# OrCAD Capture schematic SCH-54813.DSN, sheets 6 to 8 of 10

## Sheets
6 09 LEVEL SHIFT: size C
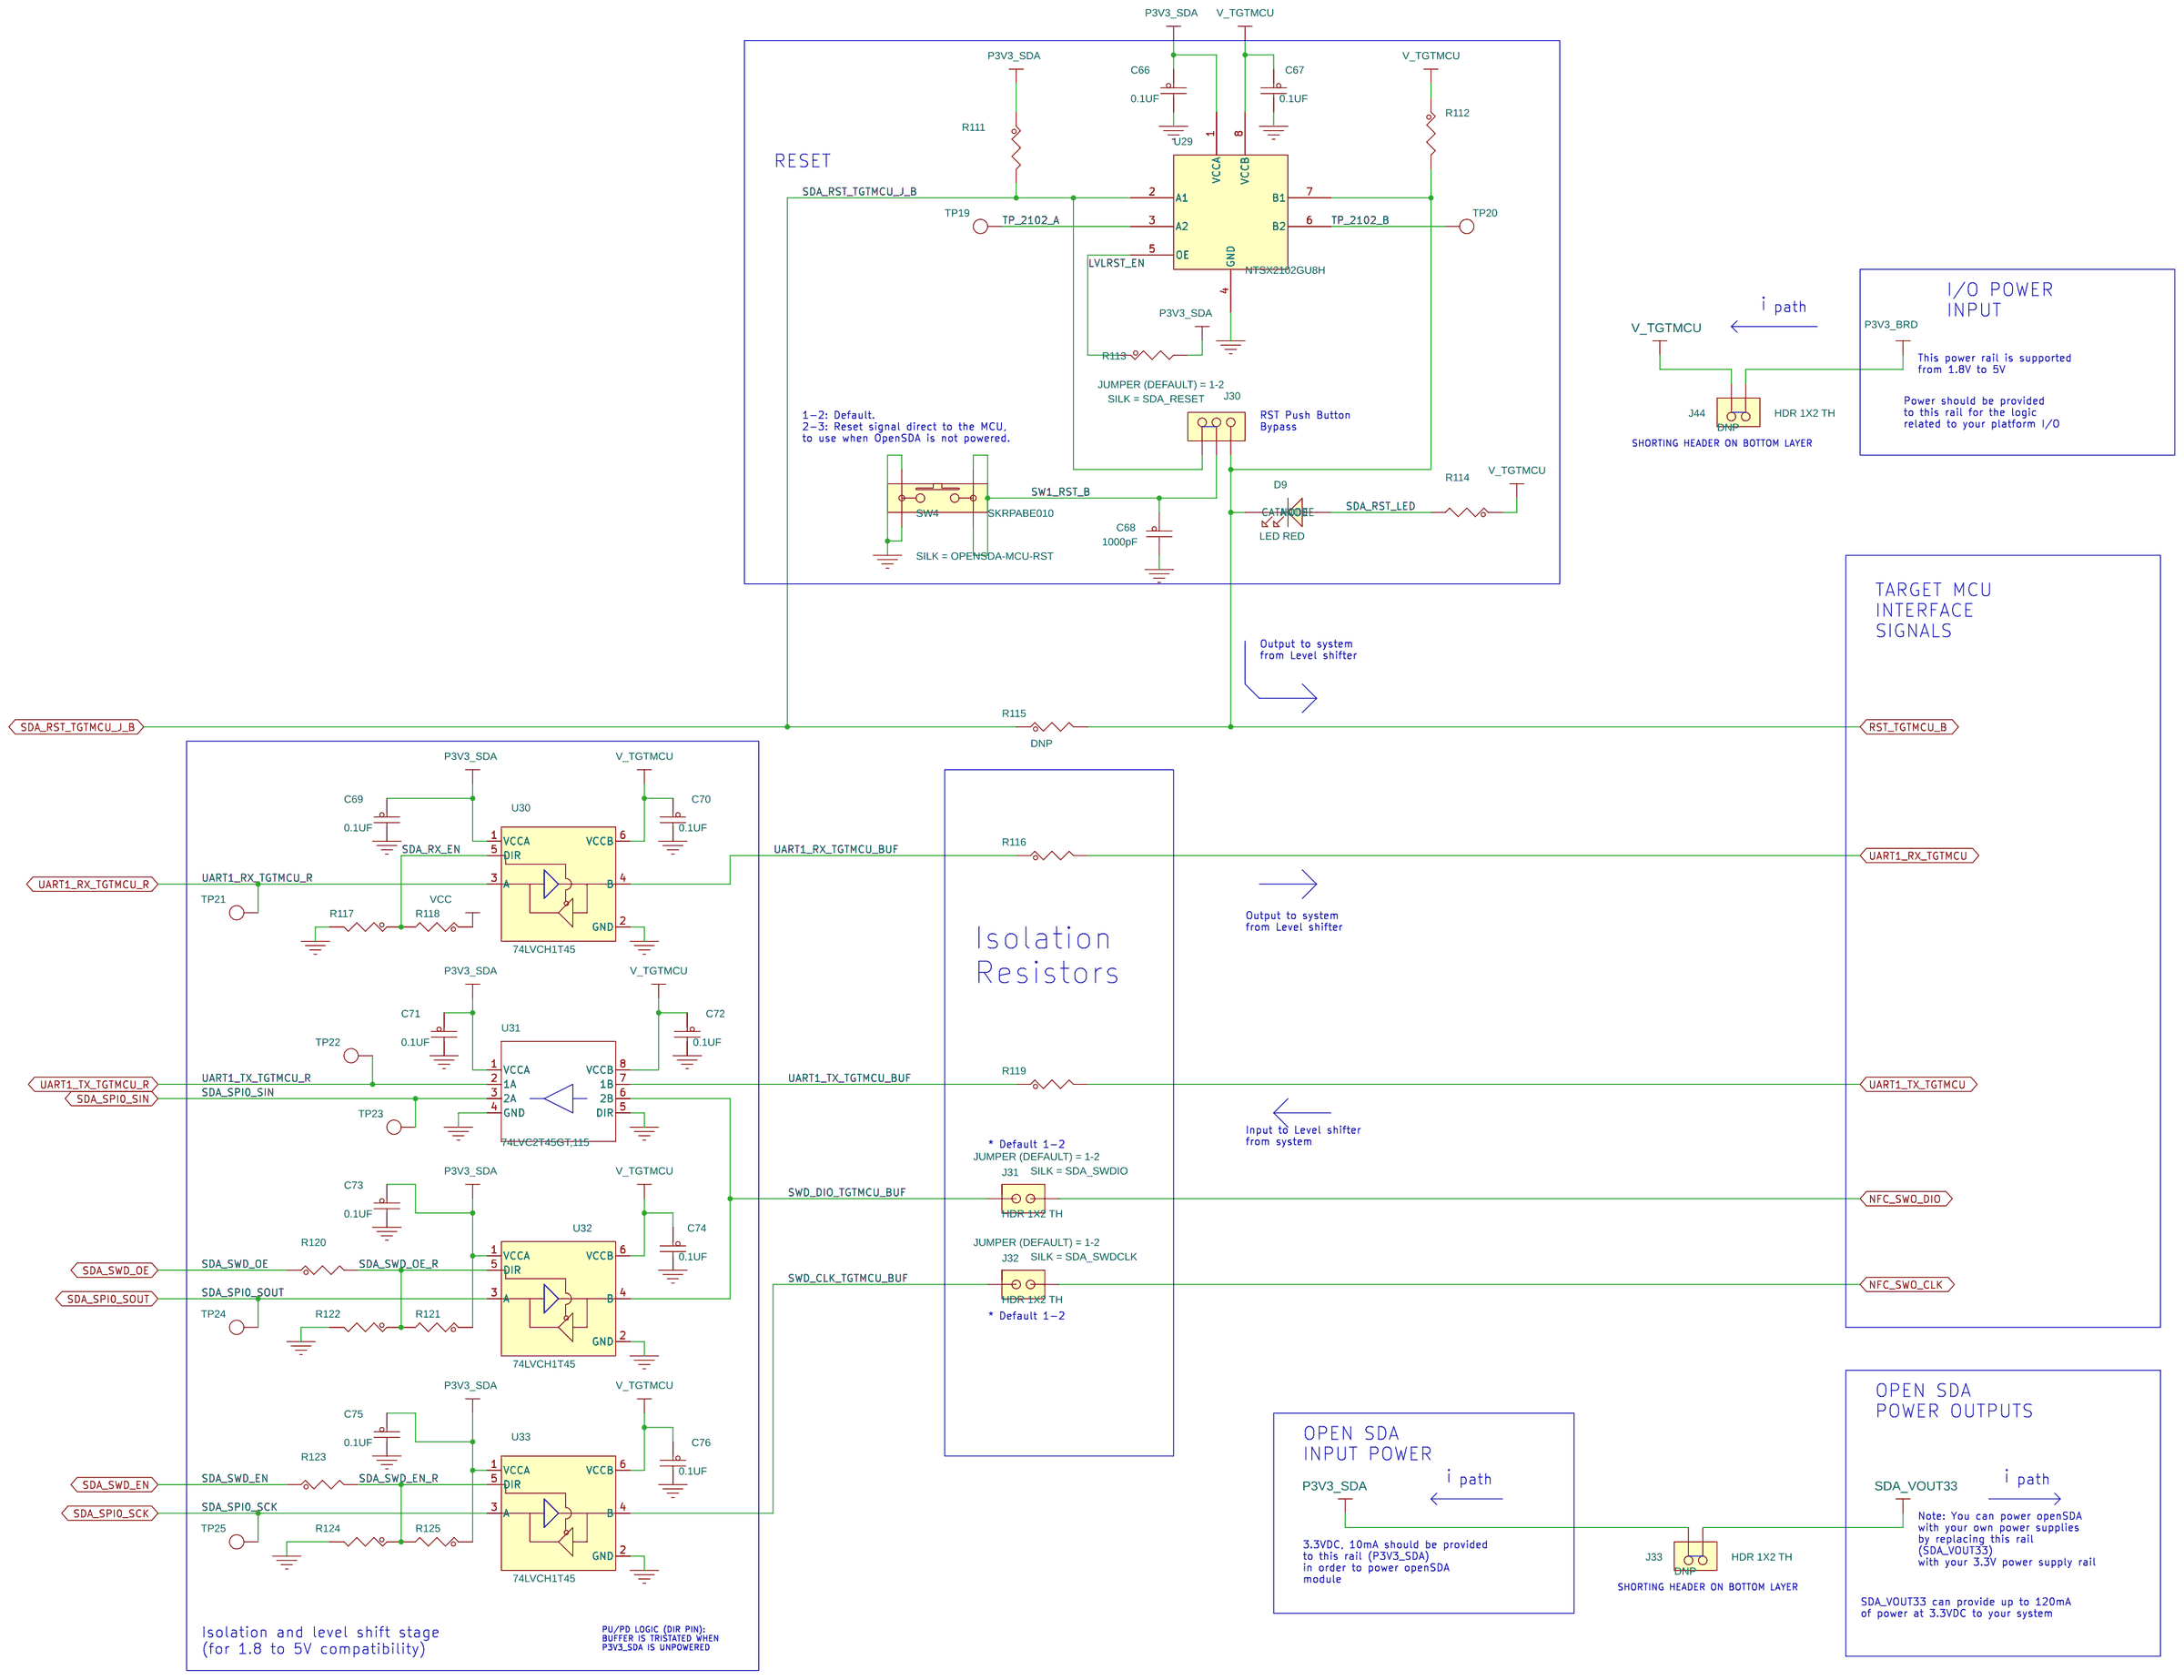
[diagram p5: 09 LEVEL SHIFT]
7 10 ARDUINO: size C
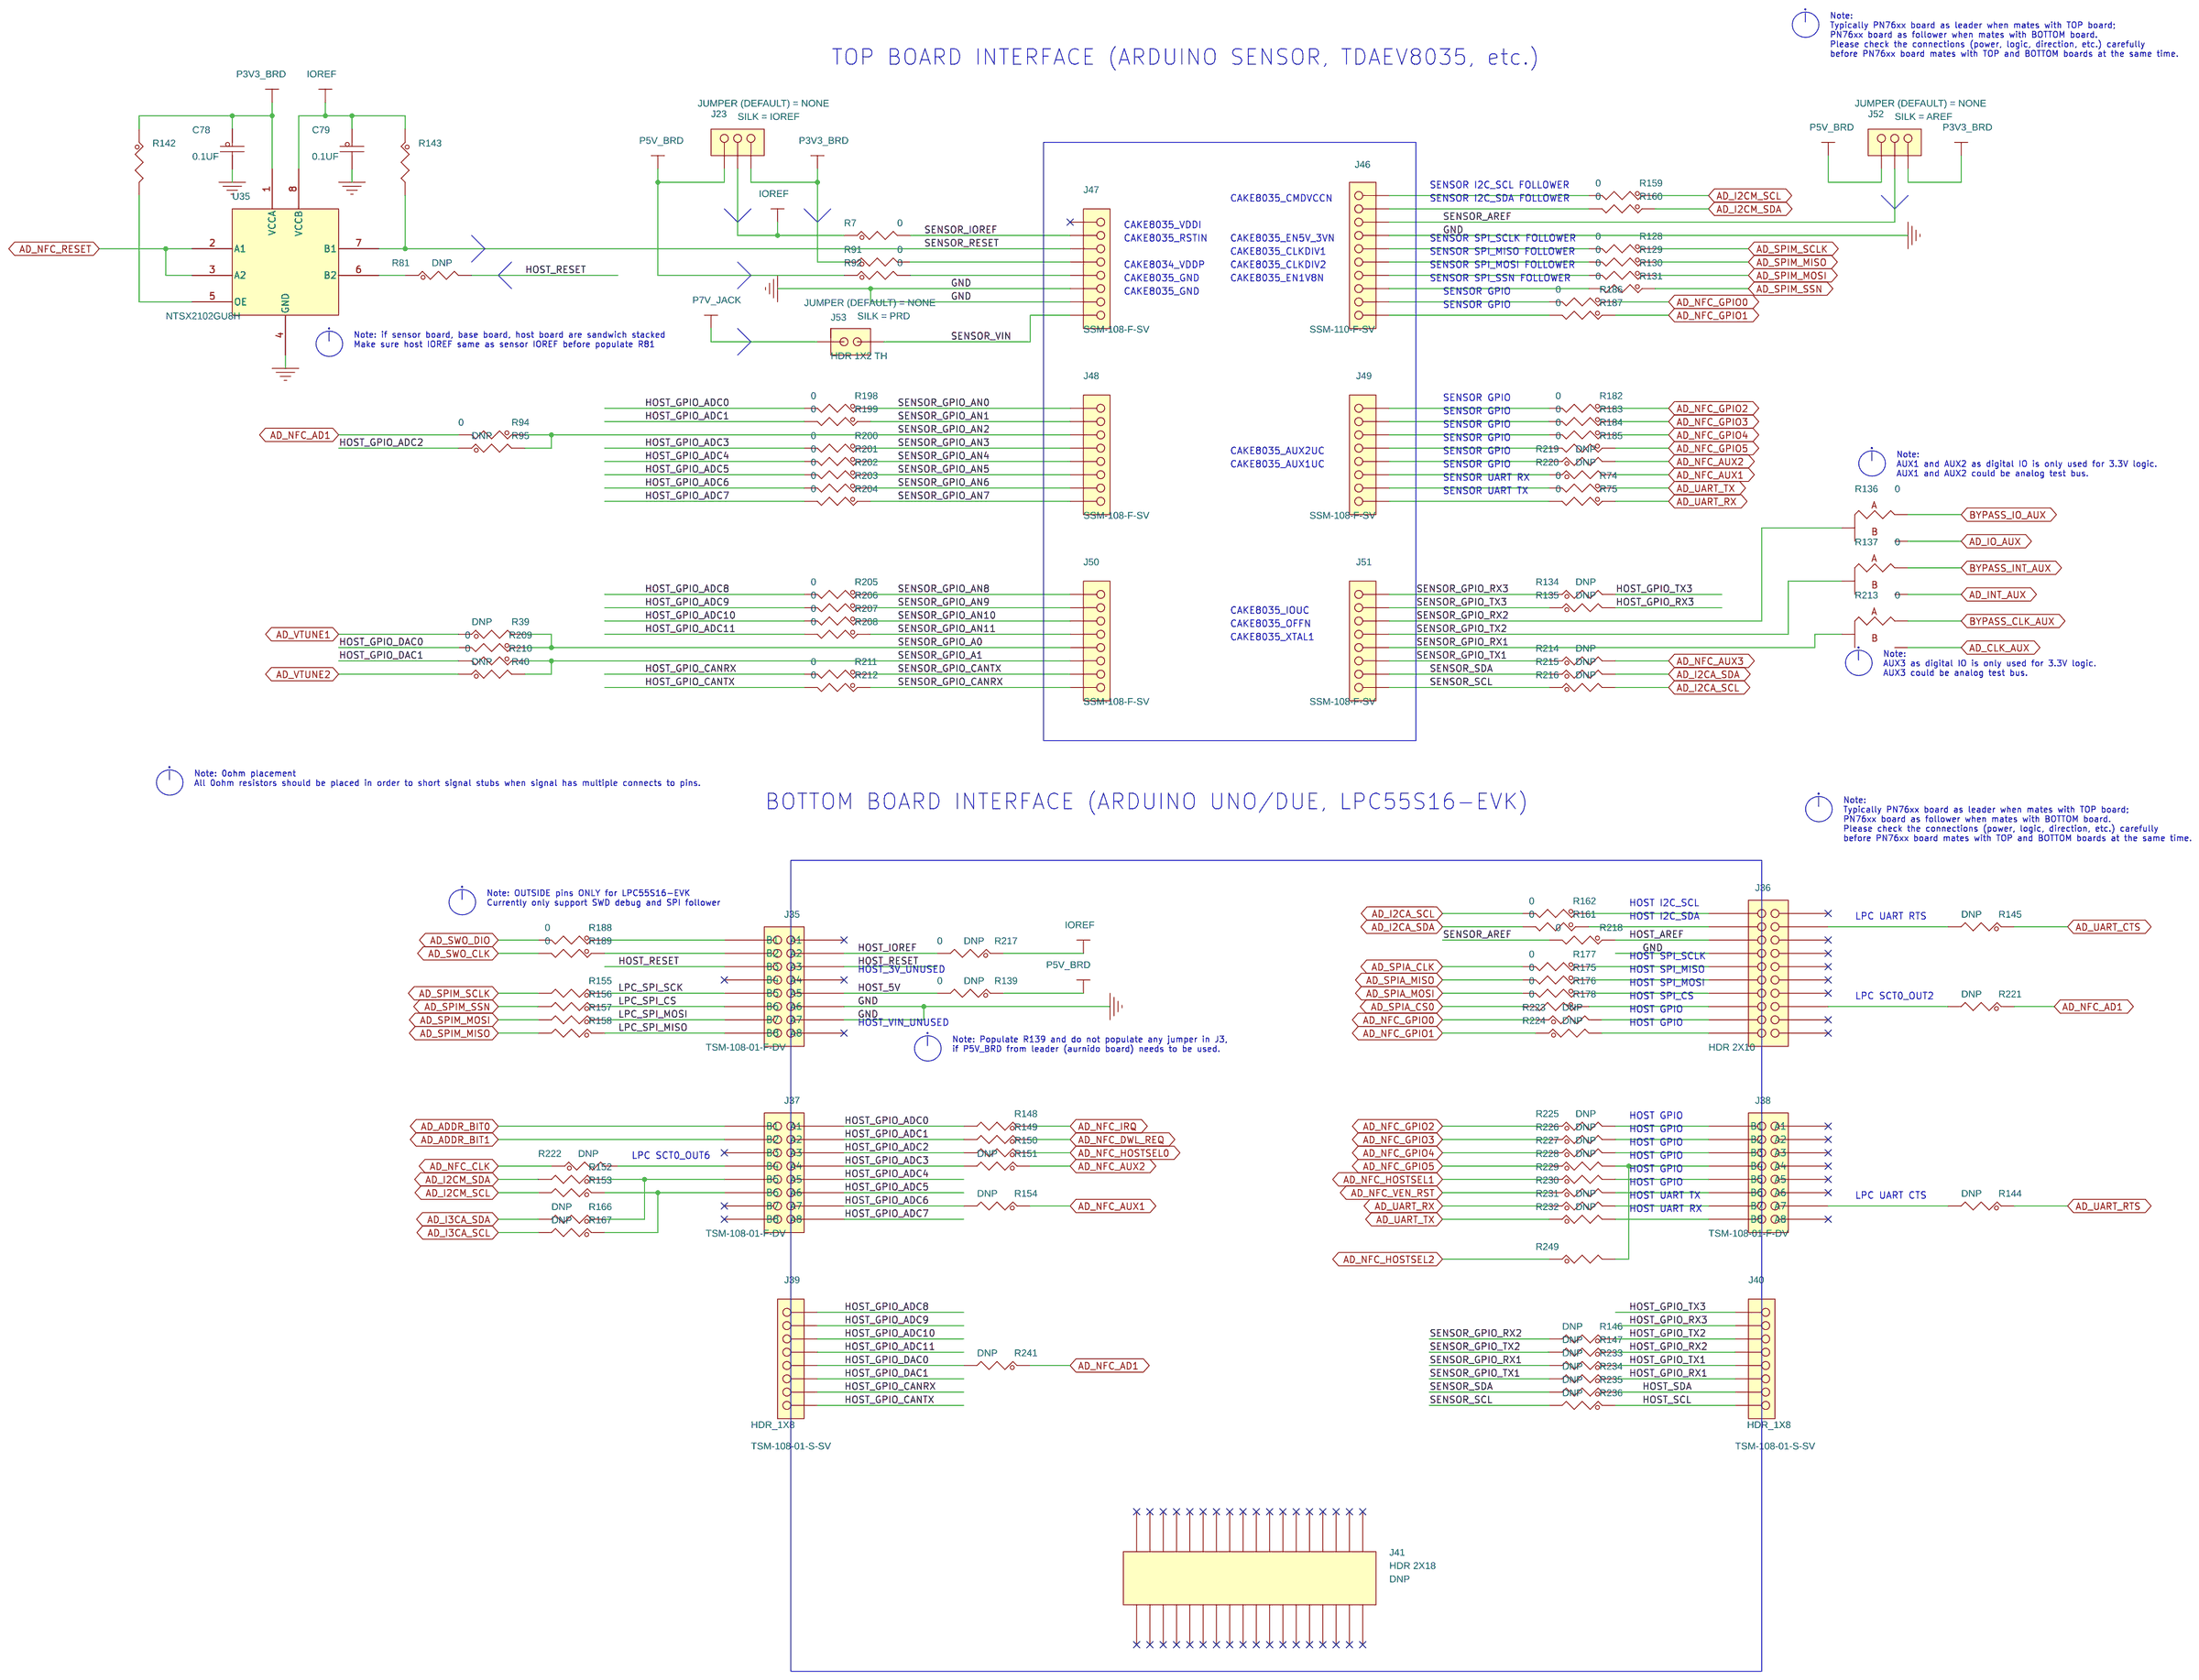
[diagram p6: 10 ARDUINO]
8 06 GPIO/DEBUG: size C
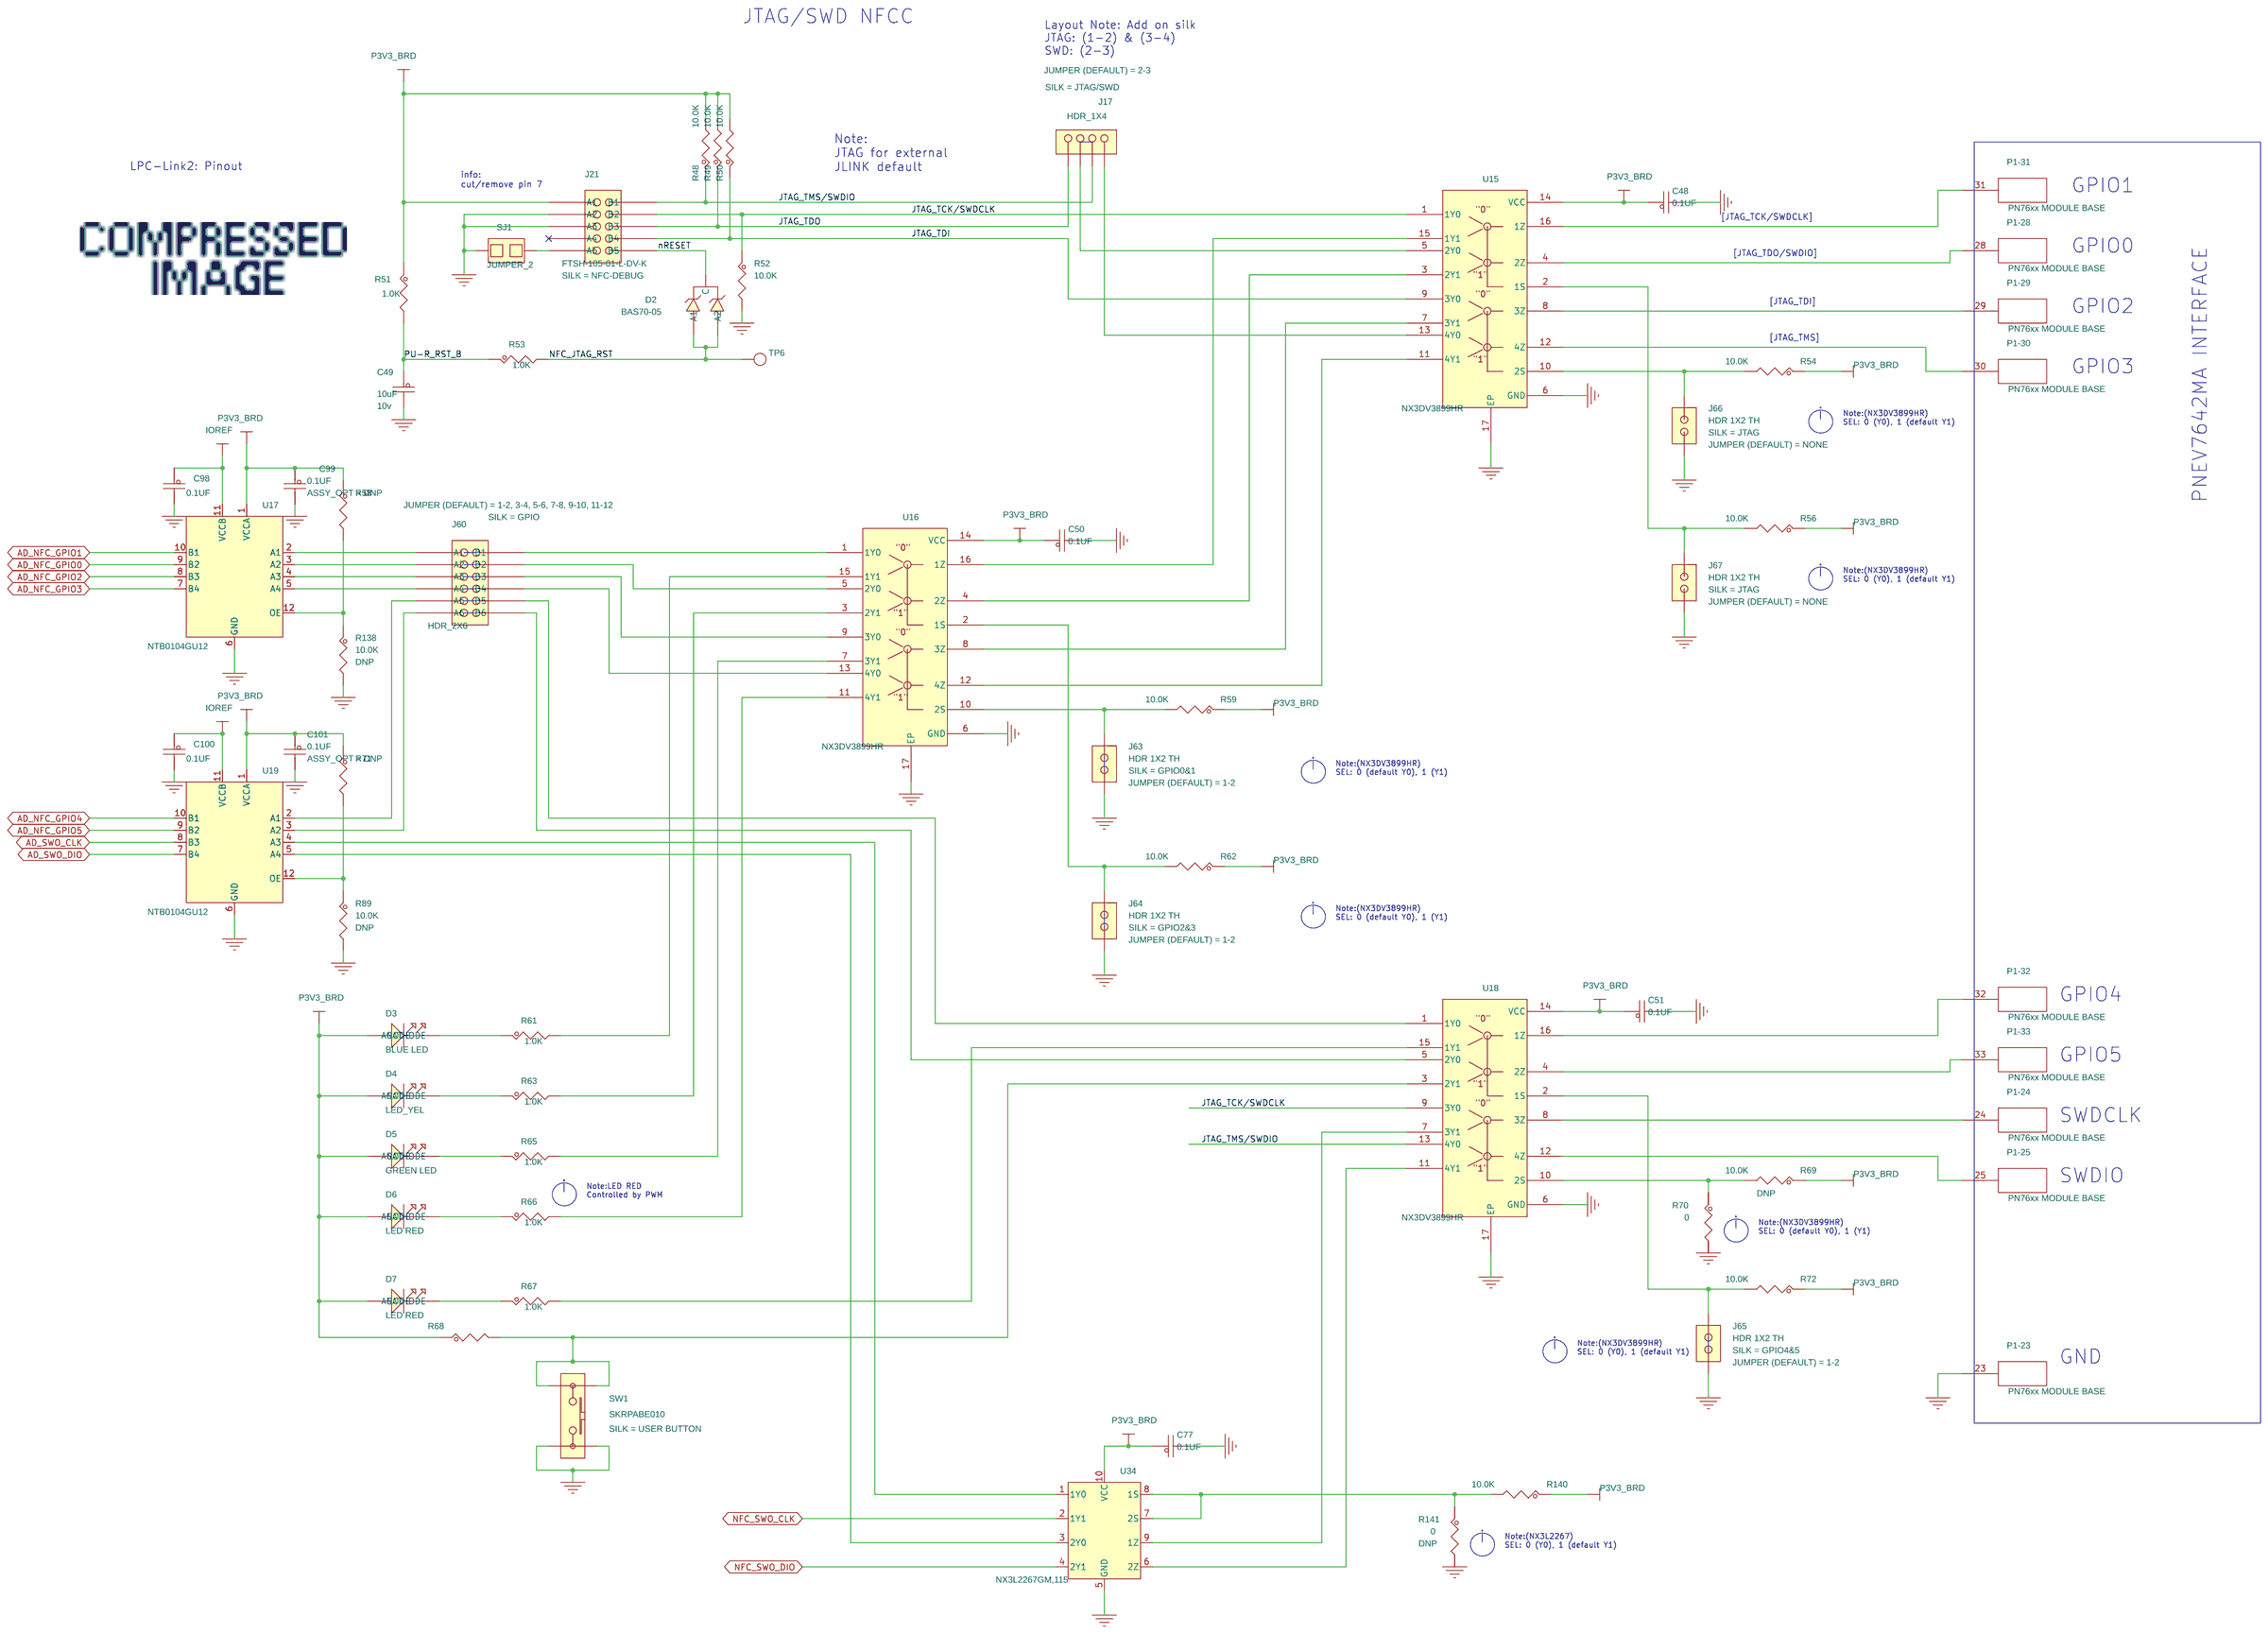
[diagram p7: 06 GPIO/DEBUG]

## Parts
sheet 06 GPIO/DEBUG
C48  0.1UF  [CC0402_25]
C49  10uF  [CC0603_OV]
C50  0.1UF  [CC0402_25]
C51  0.1UF  [CC0402_25]
C77  0.1UF  [CC0402_25]
C98  0.1UF  [CC0402_25]
C99  0.1UF  [CC0402_25]
C100  0.1UF  [CC0402_25]
C101  0.1UF  [CC0402_25]
D2  BAS70-05  [SOT23_A]
D3  BLUE LED  [LED_0603]
D4  LED_YEL  [LED_0603]
D5  GREEN LED  [led_0603_h020]
D6  LED RED  [LED_0603]
D7  LED RED  [LED_0603]
J17  HDR_1X4  [JUMP1X4-6040]
J21  FTSH-105-01-L-DV-K  [hdr205_10m_50_sm_k]
J60  HDR_2X6  [HDR206]
J63  HDR 1X2 TH  [HDR_1X2]
J64  HDR 1X2 TH  [HDR_1X2]
J65  HDR 1X2 TH  [HDR_1X2]
J66  HDR 1X2 TH  [HDR_1X2]
J67  HDR 1X2 TH  [HDR_1X2]
P1  PN76xx MODULE BASE  [module56_1p52_23x23mm]  (sections -1,-10,-11,-12,-13,-14,-15,-16,-17,-18,-19,-2,-20,-21,-22,-23,-24,-25,-26,-27,-28,-29,-3,-30,-31,-32,-33,-34,-35,-36,-37,-38,-39,-4,-40,-41,-42,-43,-44,-45,-46,-47,-48,-49,-5,-50,-51,-52,-53,-54,-55,-56,-57,-6,-7,-8,-9)
R48  10.0K  [RC0402_25]
R49  10.0K  [RC0402_25]
R50  10.0K  [RC0402_25]
R51  1.0K  [RC0402_25]
R52  10.0K  [RC0402_25]
R53  1.0K  [RC0402_25]
R54  10.0K  [RC0402_25]
R56  10.0K  [RC0402_25]
R58  4.7K  [RC0402_25]
R59  10.0K  [RC0402_25]
R61  1.0K  [RC0402_25]
R62  10.0K  [RC0402_25]
R63  1.0K  [RC0402_25]
R65  1.0K  [RC0402_25]
R66  1.0K  [RC0402_25]
R67  1.0K  [RC0402_25]
R68  10.0K  [RC0402_25]
R69  10.0K  [RC0402_25]
R70  0  [RC0603_OV]
R71  4.7K  [RC0402_25]
R72  10.0K  [RC0402_25]
R89  10.0K  [RC0402_25]
R138  10.0K  [RC0402_25]
R140  10.0K  [RC0402_25]
R141  0  [RC0603_OV]
SJ1  JUMPER_2  [jump1x2_0805]
SW1  SKRPABE010  [sw4_skrp]
TP6  TPAD_040  [TPAD_040]
U15  NX3DV3899HR  [QFN16_0P5_3X3_EP]
U16  NX3DV3899HR  [QFN16_0P5_3X3_EP]
U17  NTB0104GU12  [xqfn12_0p4_1p8x2p1]
U18  NX3DV3899HR  [QFN16_0P5_3X3_EP]
U19  NTB0104GU12  [xqfn12_0p4_1p8x2p1]
U34  NX3L2267GM,115  [XQFN10_0P5_1P65X2P1]
sheet 09 LEVEL SHIFT
C66  0.1UF  [CC0402_25]
C67  0.1UF  [CC0402_25]
C68  1000pF  [CC0402_25]
C69  0.1UF  [CC0402_25]
C70  0.1UF  [CC0402_25]
C71  0.1UF  [CC0402_25]
C72  0.1UF  [CC0402_25]
C73  0.1UF  [CC0402_25]
C74  0.1UF  [CC0402_25]
C75  0.1UF  [CC0402_25]
C76  0.1UF  [CC0402_25]
D9  LED RED  [LED_0603]
J30  HDR TH 1X3  [HDR103]
J31  HDR 1X2 TH  [HDR_1X2]
J32  HDR 1X2 TH  [HDR_1X2]
J33  HDR 1X2 TH  [SH_HDR102_BOTTOM]
J44  HDR 1X2 TH  [SH_HDR102_BOTTOM]
R111  10.0K  [RC0402_25]
R112  180K  [RC0805_OV]
R113  4.7K  [RC0402_25]
R114  100  [RC0402_25]
R115  0  [RC0603_OV]
R116  1.0K  [RC0402_25]
R117  10.0K  [RC0402_25]
R118  4.7K  [RC0402_25]
R119  1.0K  [RC0402_25]
R120  0  [RC0603_OV]
R121  4.7K  [RC0402_25]
R122  10.0K  [RC0402_25]
R123  0  [RC0603_OV]
R124  10.0K  [RC0402_25]
R125  4.7K  [RC0402_25]
SW4  SKRPABE010  [sw4_skrp]
TP19  TPAD_030  [TPAD_030]
TP20  TPAD_030  [TPAD_030]
TP21  TPAD_030  [TPAD_030]
TP22  TPAD_030  [TPAD_030]
TP23  TPAD_030  [TPAD_030]
TP24  TPAD_030  [TPAD_030]
TP25  TPAD_030  [TPAD_030]
U29  NTSX2102GU8H  [xqfn8_1p45x1p25mm]
U30  74LVCH1T45  [udfn6_1x1p5mm]
U31  74LVC2T45GT,115  [xson_8p]
U32  74LVCH1T45  [udfn6_1x1p5mm]
U33  74LVCH1T45  [udfn6_1x1p5mm]
sheet 10 ARDUINO
C78  0.1UF  [CC0402_25]
C79  0.1UF  [CC0402_25]
J23  HDR TH 1X3  [HDR103]
J35  TSM-108-01-F-DV  [hdr208_tsm_sm_450m]
J36  HDR 2X10  [CON_TSM_20M_2P54_SM]
J37  TSM-108-01-F-DV  [hdr208_tsm_sm_450m]
J38  TSM-108-01-F-DV  [hdr208_tsm_sm_450m]
J39  HDR_1X8  [HDR108_STAG_TSM_SMT]
J40  HDR_1X8  [HDR108_STAG_TSM_SMT]
J41  HDR 2X18  [hdr218_2p54_a]
J46  SSM-110-F-SV  [con1x10_2p54_ssm]
J47  SSM-108-F-SV  [con1x8_skt_2p54_ssm]
J48  SSM-108-F-SV  [con1x8_skt_2p54_ssm]
J49  SSM-108-F-SV  [con1x8_skt_2p54_ssm]
J50  SSM-108-F-SV  [con1x8_skt_2p54_ssm]
J51  SSM-108-F-SV  [con1x8_skt_2p54_ssm]
J52  HDR TH 1X3  [HDR103]
J53  HDR 1X2 TH  [HDR_1X2]
R7  0  [RC0805_OV]
R39  0  [RC0603_OV]
R40  0  [RC0603_OV]
R74  0  [RC0603_OV]
R75  0  [RC0603_OV]
R81  0  [RC0603_OV]
R91  0  [RC0805_OV]
R92  0  [RC0805_OV]
R94  0  [RC0603_OV]
R95  0  [RC0603_OV]
R128  0  [RC0603_OV]
R129  0  [RC0603_OV]
R130  0  [RC0603_OV]
R131  0  [RC0603_OV]
R134  0  [RC0603_OV]
R135  0  [RC0603_OV]
R136  0  [R603-X2]
R137  0  [R603-X2]
R139  0  [RC0805_OV]
R142  4.7K  [RC0402_25]
R143  10.0K  [RC0402_25]
R144  0  [RC0603_OV]
R145  0  [RC0603_OV]
R146  0  [RC0603_OV]
R147  0  [RC0603_OV]
R148  0  [RC0603_OV]
R149  0  [RC0603_OV]
R150  0  [RC0603_OV]
R151  0  [RC0603_OV]
R152  0  [RC0603_OV]
R153  0  [RC0603_OV]
R154  0  [RC0603_OV]
R155  0  [RC0603_OV]
R156  0  [RC0603_OV]
R157  0  [RC0603_OV]
R158  0  [RC0603_OV]
R159  0  [RC0603_OV]
R160  0  [RC0603_OV]
R161  0  [RC0603_OV]
R162  0  [RC0603_OV]
R166  0  [RC0603_OV]
R167  0  [RC0603_OV]
R175  0  [RC0603_OV]
R176  0  [RC0603_OV]
R177  0  [RC0603_OV]
R178  0  [RC0603_OV]
R182  0  [RC0603_OV]
R183  0  [RC0603_OV]
R184  0  [RC0603_OV]
R185  0  [RC0603_OV]
R186  0  [RC0603_OV]
R187  0  [RC0603_OV]
R188  0  [RC0603_OV]
R189  0  [RC0603_OV]
R198  0  [RC0603_OV]
R199  0  [RC0603_OV]
R200  0  [RC0603_OV]
R201  0  [RC0603_OV]
R202  0  [RC0603_OV]
R203  0  [RC0603_OV]
R204  0  [RC0603_OV]
R205  0  [RC0603_OV]
R206  0  [RC0603_OV]
R207  0  [RC0603_OV]
R208  0  [RC0603_OV]
R209  0  [RC0603_OV]
R210  0  [RC0603_OV]
R211  0  [RC0603_OV]
R212  0  [RC0603_OV]
R213  0  [R603-X2]
R214  0  [RC0603_OV]
R215  0  [RC0603_OV]
R216  0  [RC0603_OV]
R217  0  [RC0805_OV]
R218  0  [RC0603_OV]
R219  0  [RC0603_OV]
R220  0  [RC0603_OV]
R221  0  [RC0603_OV]
R222  0  [RC0603_OV]
R223  0  [RC0603_OV]
R224  0  [RC0603_OV]
R225  0  [RC0603_OV]
R226  0  [RC0603_OV]
R227  0  [RC0603_OV]
R228  0  [RC0603_OV]
R229  0  [RC0603_OV]
R230  0  [RC0603_OV]
R231  0  [RC0603_OV]
R232  0  [RC0603_OV]
R233  0  [RC0603_OV]
R234  0  [RC0603_OV]
R235  0  [RC0603_OV]
R236  0  [RC0603_OV]
R241  0  [RC0603_OV]
R249  0  [RC0603_OV]
U35  NTSX2102GU8H  [xqfn8_1p45x1p25mm]

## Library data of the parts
C48 C50 C51 C66 C67 C69-C79 C98 C100 = CAP_NP: CAP CER 0.1UF 50V 10% X5R 0402; AGILE_PN: 150-79249; CAD_APPROVED: Yes; FPLIST: CC0402_25,CC0402_HD,0402_CC,capc0402_l; HEIGHT: 0.55MM; MFG_NAME01: MURATA; MFG_PN01: GRM155R61H104KE19; ROHS: Yes; Rated Voltage: 50V; TOL: 10%; Temp Range: -55C to +85C; Tolerance: 10%; VOLTAGE: 50V
C49 = CAP_NP: CAP CER 10UF 10V 10% X5R 0603; AGILE_PN: 150-78675; CAD_APPROVED: Yes; FPLIST: CC0603_OV,CC0603,0603_CC_NSP; HEIGHT: 1.016MM; MFG_NAME01: MURATA; MFG_PN01: GRM188R61A106KE69D; ROHS: Yes; Rated Voltage: 10V; Temp Range: -55C to +85C; Temp_Range: -55°C to +85°C; Tolerance: 10%; VOLTAGE: 10v
C99 C101 = CAP_NP: CAP CER 0.1UF 50V 10% X5R 0402; AGILE_PN: 150-79249; ASSY_OPT: DNP; CAD_APPROVED: Yes; FPLIST: CC0402_25,CC0402_HD,0402_CC,capc0402_l; HEIGHT: 0.55MM; MFG_NAME01: MURATA; MFG_PN01: GRM155R61H104KE19; ROHS: Yes; Rated Voltage: 50V; TOL: 10%; Temp Range: -55C to +85C; Tolerance: 10%; VOLTAGE: 50V
D2 = DIODE_DUAL_SCH_3P: DIODE SCH DUAL 70mA 410mV AEC-Q101 SOT23; AGILE_PN: 480-79750; CAD_APPROVED: Yes; HEIGHT: 1.1MM; MFG_NAME01: NEXPERIA; MFG_PN01: BAS70-05,215; REQUESTED_COMPLETION_DATE: Not an expedite request; ROHS: Yes; Rated Voltage: 0.41V; Temp Range: -65C to +150C; Temp_Range: -65C to +150C; VOLTAGE: 0.41V
D3 = LED: LED BLUE CLEAR SGL 20MA 3.2V 0603 SMT; AGILE_PN: 370-76775; CAD_APPROVED: Yes; HEIGHT: 0.8MM; MFG_NAME01: WURTH ELEKTRONIK EISOS GMBH & CO. KG (ELECTRONIC & ELECTROMEHANICAL COMP); MFG_PN01: 150060BS75000; Rated Voltage: 3.2V; Temp Range: -40°C to 85°C; VOLTAGE: 3.2V
D4 = LED: LED YELLOW CLEAR 20mA 2V 0603 SMT; AGILE_PN: 370-76774; CAD_APPROVED: Yes; HEIGHT: 0.8MM; MFG_NAME01: WURTH ELEKTRONIK EISOS GMBH & CO. KG (ELECTRONIC & ELECTROMEHANICAL COMP); MFG_PN01: 150060YS75000; Rated Voltage: 2V; Temp Range: -40C - 80C; VOLTAGE: 2V
D5 = LED: LED GRN SGL 20MA 2V SMT 0603; 3D_Mechanical_Footprint_File: http://fcl.am.freescale.net/ALLEGRO/step/led_0603_h020.STEP; AGILE_PN: 370-76819; CAD_APPROVED: YES; HEIGHT: 0.5 mm; MFG_NAME01: WURTH ELEKTRONIK EISOS GMBH & CO. KG (ELECTRONIC & ELECTROMEHANICAL COMP); MFG_PN01: 150060VS55040; Package Size: 0603 (1608 metric)
D6 D7 D9 = LED: LED BRIGHT RED CLEAR SGL 2V 20MA SMT 0603; AGILE_PN: 370-76779; CAD_APPROVED: Yes; HEIGHT: 0.80MM; MFG_NAME01: WURTH ELEKTRONIK EISOS GMBH & CO. KG (ELECTRONIC & ELECTROMEHANICAL COMP); MFG_PN01: 150060RS75000; Rated Voltage: 2V; VOLTAGE: 2V
J17 = CONN_HDR_4X1: HDR 1X4 TH 100MIL SP  336H AU 100L; 3D_Mechanical_Footprint_File: http://fcl.am.freescale.net/ALLEGRO/step/jump1x4-6040.STEP; AGILE_PN: 210-75688; CAD_APPROVED: Yes; HEIGHT: 8.4mm; JUMPER (DEFAULT): 2-3; MFG_NAME01: SAMTEC; MFG_PN01: TSW-104-07-G-S; ROHS: Yes; SILK: JTAG/SWD; VOLTAGE: 450 - 550 VAC
J21 = CONN_HDR_5X2: HDR 2X5 SMT 50MIL CTR 246H AU; 3D_Mechanical_Footprint_File: http://fcl.am.freescale.net/ALLEGRO/step/hdr205_10m_50_sm_k.STEP; AGILE_PN: 211-79478; ASSY_NOTE: CUT PIN 7; CAD_APPROVED: Yes; HEIGHT: 6.25MM; MFG_NAME01: SAMTEC; ROHS: Yes; SILK: NFC-DEBUG
J60 = CONN_HDR_6X2: HDR 2X6 TH 100MIL CTR 338H AU 100L; 3D_Mechanical_Footprint_File: http://fcl.am.freescale.net/ALLEGRO/step/hdr206_8p68mm.STEP; AGILE_PN: 210-81086; CAD_APPROVED: Yes; HEIGHT: 8.59MM; JUMPER (DEFAULT): 1-2, 3-4, 5-6, 7-8, 9-10, 11-12; MFG_NAME01: SAMTEC; MFG_PN01: TSW-106-07-F-D; ROHS: Yes; SILK: GPIO; Temp Range: -55°C to +125°C
J63 = HDR_1X2_TH: HDR 1X2 TH 100MIL SP 339H AU 98L; 3D_Mechanical_Footprint_File: http://fcl.am.freescale.net/ALLEGRO/step/hdr102_338h.STEP; AGILE_PN: 210-75439; CAD_APPROVED: YES; FPLIST: HDR102,SH_HDR102_BOTTOM; HEIGHT: 8.71 MM; JUMPER (DEFAULT): 1-2; MFG_NAME01: SAMTEC; MFG_PN01: TSW-102-07-G-S; ROHS: Yes; SILK: GPIO0&1; Temp Range: -55°C to +125°C
J64 = HDR_1X2_TH: HDR 1X2 TH 100MIL SP 339H AU 98L; 3D_Mechanical_Footprint_File: http://fcl.am.freescale.net/ALLEGRO/step/hdr102_338h.STEP; AGILE_PN: 210-75439; CAD_APPROVED: YES; FPLIST: HDR102,SH_HDR102_BOTTOM; HEIGHT: 8.71 MM; JUMPER (DEFAULT): 1-2; MFG_NAME01: SAMTEC; MFG_PN01: TSW-102-07-G-S; ROHS: Yes; SILK: GPIO2&3; Temp Range: -55°C to +125°C
J65 = HDR_1X2_TH: HDR 1X2 TH 100MIL SP 339H AU 98L; 3D_Mechanical_Footprint_File: http://fcl.am.freescale.net/ALLEGRO/step/hdr102_338h.STEP; AGILE_PN: 210-75439; CAD_APPROVED: YES; FPLIST: HDR102,SH_HDR102_BOTTOM; HEIGHT: 8.71 MM; JUMPER (DEFAULT): 1-2; MFG_NAME01: SAMTEC; MFG_PN01: TSW-102-07-G-S; ROHS: Yes; SILK: GPIO4&5; Temp Range: -55°C to +125°C
J66 J67 = HDR_1X2_TH: HDR 1X2 TH 100MIL SP 339H AU 98L; 3D_Mechanical_Footprint_File: http://fcl.am.freescale.net/ALLEGRO/step/hdr102_338h.STEP; AGILE_PN: 210-75439; CAD_APPROVED: YES; FPLIST: HDR102,SH_HDR102_BOTTOM; HEIGHT: 8.71 MM; JUMPER (DEFAULT): NONE; MFG_NAME01: SAMTEC; MFG_PN01: TSW-102-07-G-S; ROHS: Yes; SILK: JTAG; Temp Range: -55°C to +125°C
P1 = TP_RECT_56P_EP: NFC MODULE 4X14 23X23MM NO PART TO ORDER; AGILE_PN: 510-78458; CAD_APPROVED: Yes; HEIGHT: 2.35 MM; ROHS: Yes
R48-R50 R52 = RES: RES MF 10.0K 1/16W 1% AEC-Q200 0402; AGILE_PN: 470-75416; CAD_APPROVED: Yes; FPLIST: RC0402_25,RC0402_HD,0402_CC; HEIGHT: 0.4MM; MFG_NAME01: KOA SPEER; MFG_PN01: RK73H1ETTP1002F; ROHS: Yes; Temp Range: –55 °C to +155 °C; Tolerance: 1%
R51 R53 R61 R63 R65-R67 = RES: RES MF 1.0K 1/16W 1% 0402; AGILE_PN: 470-76037; CAD_APPROVED: Yes; FPLIST: RC0402_25,RC0402_HD,RC0402_X2,0402_CC; HEIGHT: 0.4MM; MFG_NAME01: VISHAY; MFG_PN01: CRCW04021K00FKEDC; ROHS: Yes; Tolerance: 1%; VOLTAGE: 1/16W
R54 R56 R59 R62 R72 R140 = RES: RES MF 10.0K 1/16W 1% AEC-Q200 0402; AGILE_PN: 470-75416; CAD_APPROVED: Yes; FPLIST: RC0402_25,RC0402_HD,0402_CC; HEIGHT: 0.4MM; MFG_NAME01: KOA SPEER; MFG_PN01: RK73H1ETTP1002F; ROHS: Yes; SIGNAL_MODEL: DEFAULT_RESISTOR_10000OHM_2_1; TOL: 5%; Temp Range: –55 °C to +155 °C; Tolerance: 1%
R58 R71 R113 R118 R121 R125 R142 = RES: RES MF 4.70K 1/16W 1% 0402; AGILE_PN: 470-75418; CAD_APPROVED: Yes; FPLIST: RC0402_25,RC0402_HD,0402_CC; HEIGHT: 0.4mm; MFG_NAME01: WALSIN TECHNOLOGY CORP.; MFG_PN01: WR04X4701FTL; ROHS: Yes; TOL: 1%; Tolerance: 1%; VOLTAGE: 1/16W
R68 R111 R117 R122 R124 R143 = RES: RES MF 10.0K 1/16W 1% AEC-Q200 0402; AGILE_PN: 470-75416; CAD_APPROVED: Yes; FPLIST: RC0402_25,RC0402_HD,0402_CC; HEIGHT: 0.4MM; MFG_NAME01: KOA SPEER; MFG_PN01: RK73H1ETTP1002F; ROHS: Yes; TOL: 5%; Temp Range: –55 °C to +155 °C; Tolerance: 1%
R69 R89 R138 = RES: RES MF 10.0K 1/16W 1% AEC-Q200 0402; AGILE_PN: 470-75416; ASSY_OPT: DNP; CAD_APPROVED: Yes; FPLIST: RC0402_25,RC0402_HD,0402_CC; HEIGHT: 0.4MM; MFG_NAME01: KOA SPEER; MFG_PN01: RK73H1ETTP1002F; ROHS: Yes; SIGNAL_MODEL: DEFAULT_RESISTOR_10000OHM_2_1; TOL: 5%; Temp Range: –55 °C to +155 °C; Tolerance: 1%
R70 R74 R75 R94 R128-R131 R159-R162 R175-R178 R182-R189 R198-R212 R218 = RES: RES MF ZERO OHM 1/10W -- 0603; AGILE_PN: 470-80866; CAD_APPROVED: Yes; FPLIST: RC0603_OV,RC0603,R603-X2,0603_CC; HEIGHT: 0.6MM; MFG_NAME01: YAGEO AMERICA; MFG_PN01: RC0603FR-070RL; ROHS: Yes; TOL: 1%; Temp Range: –55 °C to +155 °C
R141 = RES: RES MF ZERO OHM 1/10W -- 0603; AGILE_PN: 470-80866; ASSY_OPT: DNP; CAD_APPROVED: Yes; FPLIST: RC0603_OV,RC0603,R603-X2,0603_CC; HEIGHT: 0.6MM; MFG_NAME01: YAGEO AMERICA; MFG_PN01: RC0603FR-070RL; ROHS: Yes; TOL: 1%; Temp Range: –55 °C to +155 °C
SJ1 = 2-PIN_PAD: JUMPER 2 PAD 0805 SMT, NO PART TO ORDER; AGILE_PN: 211-79320; CAD_APPROVED: Yes; HEIGHT: 0.1MM; MFG_NAME01: NA; MFG_PN01: NO PART TO ORDER1; ROHS: Yes
SW1 = SW_TC_SPST_4P: SW SPST PB SMT 16V 20MA; 3D_Mechanical_Footprint_File: http://fcl.am.freescale.net/ALLEGRO/step/sw4_skrp.step; AGILE_PN: 510-75638; CAD_APPROVED: Yes; HEIGHT: 2.5MM; MFG_NAME01: ALPS ELECTRIC (USA) INC.; ROHS: Yes; SILK: USER BUTTON; VOLTAGE: 16V
TP6 = TESTLOOP: TEST POINT PAD 40MIL DIA SMT, NO PART TO ORDER; AGILE_PN: 211-76643; CAD_APPROVED: Yes; HEIGHT: 0.1MM; MFG_NAME01: NOTACOMPONENT; MFG_PN01: NOTACOMPONENT; ROHS: Yes
U15 U16 U18 = NX3DV3899HR: IC LIN SW DPDT 1.4-4.3V QFN16; 3D_Mechanical_Footprint_File: http://fcl.am.freescale.net/ALLEGRO/step/qfn16_0p5_3x3_ep.STEP; AGILE_PN: 315-80655; CAD_APPROVED: Yes; HEIGHT: 0.5MM; MFG_NAME01: NXP SEMICONDUCTORS; MFG_PN01: NX3DV3899HRZ; ROHS: Yes; VOLTAGE: 1.4-4.3V
U17 U19 = NTB0104GU12_12P: IC DUAL VXLTR XCVR 4BIT 1.2-3.6/1.65-5.5V XQFN12; 3D_Mechanical_Footprint_File: http://fcl.am.freescale.net/ALLEGRO/step/xqfn12_0p4_1p8x2p1.step; AGILE_PN: 312-81869; CAD_APPROVED: Yes; HEIGHT: 0.5MM; MFG_NAME01: NXP SEMICONDUCTORS; ROHS: Yes; Temp Range: -40C to +125C; VOLTAGE: 1.2-3.6/1.65-5.5V
U34 = NX3L2267GM_QFN10: IC ANALOG SW DUAL SPDT 1.4-4.3V XQFN10; 3D_Mechanical_Footprint_File: http://fcl.am.freescale.net/ALLEGRO/step/xqfn10_0p5_1p65x2p1.step; AGILE_PN: 315-81532; CAD_APPROVED: Yes; HEIGHT: 0.5 MM; MFG_NAME01: NXP SEMICONDUCTORS; ROHS: Yes; Temp Range: -40°C to +125°C; VOLTAGE: 1.4-4.3V
C68 = CAP_NP: CAP CER 1000pF 50V 10% X7R AEC-Q200 0402; AGILE_PN: 150-79040; CAD_APPROVED: Yes; FPLIST: CC0402_25,CC0402_HD,0402_CC; HEIGHT: 0.55MM; MFG_NAME01: MURATA; MFG_PN01: GCM155R71H102KA37D; Package Size: 0402; Package Type: Paper Tape; ROHS: Yes; Rated Voltage: 50V; Temp Range: -55C to +125C; Tolerance: 10%; VOLTAGE: 50V
J30 = CONN_HDR_3X1: HDR 1X3 TH 100MIL SP 339H AU 100L; 3D_Mechanical_Footprint_File: http://fcl.am.freescale.net/ALLEGRO/step/hdr103.STEP; AGILE_PN: 210-75726; CAD_APPROVED: Yes; HEIGHT: 8.65MM; JUMPER (DEFAULT): 1-2; MFG_NAME01: SAMTEC; MFG_PN01: TSW-103-07-G-S; Package Size: 7.62 x 2.54 mm; ROHS: Yes; SILK: SDA_RESET; Temp Range: -55°C to +125°C; VOLTAGE: 450 - 550 VAC
J31 = HDR_1X2_TH: HDR 1X2 TH 100MIL SP 339H AU 98L; 3D_Mechanical_Footprint_File: http://fcl.am.freescale.net/ALLEGRO/step/hdr102_338h.STEP; AGILE_PN: 210-75439; CAD_APPROVED: YES; FPLIST: HDR102,SH_HDR102_BOTTOM; HEIGHT: 8.71 MM; JUMPER (DEFAULT): 1-2; MFG_NAME01: SAMTEC; MFG_PN01: TSW-102-07-G-S; ROHS: Yes; SILK: SDA_SWDIO; Temp Range: -55°C to +125°C
J32 = HDR_1X2_TH: HDR 1X2 TH 100MIL SP 339H AU 98L; 3D_Mechanical_Footprint_File: http://fcl.am.freescale.net/ALLEGRO/step/hdr102_338h.STEP; AGILE_PN: 210-75439; CAD_APPROVED: YES; FPLIST: HDR102,SH_HDR102_BOTTOM; HEIGHT: 8.71 MM; JUMPER (DEFAULT): 1-2; MFG_NAME01: SAMTEC; MFG_PN01: TSW-102-07-G-S; ROHS: Yes; SILK: SDA_SWDCLK; Temp Range: -55°C to +125°C
J33 J44 = CONN_HDR_2X1: HDR 1X2 TH 100MIL SP 339H AU 98L; 3D_Mechanical_Footprint_File: http://fcl.am.freescale.net/ALLEGRO/step/hdr102_338h.STEP; AGILE_PN: 210-75439; ASSY_OPT: DNP; CAD_APPROVED: YES; FPLIST: HDR102,SH_HDR102_BOTTOM; HEIGHT: 8.71 MM; MFG_NAME01: SAMTEC; MFG_PN01: TSW-102-07-G-S; ROHS: Yes; Temp Range: -55°C to +125°C
R112 = RES: RES MF 180K 1/8W 1% 0805; AGILE_PN: 470-75567; CAD_APPROVED: Yes; FPLIST: RC0805_OV,RC0805,0805_CC; HEIGHT: 0.7 MM; MFG_NAME01: BOURNS; MFG_PN01: CR0805-FX-1803ELF; ROHS: Yes; SIGNAL_MODEL: DEFAULT_RESISTOR_180000OHM_2_1; TOL: 1%; Tolerance: 1%
R114 = RES: RES MF 100 OHM 1/16W 5% 0402; AGILE_PN: 470-75591; CAD_APPROVED: Yes; FPLIST: RC0402_25,RC0402_HD,RC0402_X2,0402_CC; HEIGHT: 0.45mm; MFG_NAME01: NIC COMPONENTS CORP; MFG_PN01: NRCL04J101TRF; ROHS: Yes; TOL: 1%; Tolerance: 5%
R39 R40 R81 R95 R115 R134 R135 R144-R147 R151 R154 R166 R167 R214-R216 R219-R228 R231-R236 R241 = RES: RES MF ZERO OHM 1/10W -- 0603; AGILE_PN: 470-80866; ASSY_OPT: DNP; CAD_APPROVED: Yes; FPLIST: RC0603_OV,RC0603,R603-X2,0603_CC,IND_0603HP_NSP,CC0603_OV_NSP; HEIGHT: 0.6MM; MFG_NAME01: YAGEO AMERICA; MFG_PN01: RC0603FR-070RL; ROHS: Yes; TOL: 5%; Temp Range: –55 °C to +155 °C
R116 R119 = RES: RES MF 1.0K 1/16W 1% 0402; AGILE_PN: 470-76037; CAD_APPROVED: Yes; FPLIST: RC0402_25,RC0402_HD,RC0402_X2,0402_CC; HEIGHT: 0.4MM; MFG_NAME01: VISHAY; MFG_PN01: CRCW04021K00FKEDC; ROHS: Yes; TOL: 1%; Tolerance: 1%; VOLTAGE: 1/16W
R120 R123 = RES: RES MF ZERO OHM 1/10W -- 0603; AGILE_PN: 470-80866; CAD_APPROVED: Yes; FPLIST: RC0603_OV,RC0603,R603-X2,0603_CC,IND_0603HP_NSP,CC0603_OV_NSP; HEIGHT: 0.6MM; MFG_NAME01: YAGEO AMERICA; MFG_PN01: RC0603FR-070RL; ROHS: Yes; Temp Range: –55 °C to +155 °C
SW4 = SW_TC_SPST_4P: SW SPST PB SMT 16V 20MA; 3D_Mechanical_Footprint_File: http://fcl.am.freescale.net/ALLEGRO/step/sw4_skrp.step; AGILE_PN: 510-75638; CAD_APPROVED: Yes; HEIGHT: 2.5MM; MFG_NAME01: ALPS ELECTRIC (USA) INC.; ROHS: Yes; SILK: OPENSDA-MCU-RST; VOLTAGE: 16V
TP19-TP25 = TESTLOOP: TEST POINT PAD 30MIL DIA SMT, NO PART TO ORDER; 3D_Mechanical_Footprint_File: http://fcl.am.freescale.net/ALLEGRO/step/tpad_030.STEP; AGILE_PN: 211-76642; CAD_APPROVED: Yes; HEIGHT: 0.1MM; MFG_NAME01: NOTACOMPONENT; MFG_PN01: NOTACOMPONENT; ROHS: Yes
U29 U35 = NTSX2102GD: IC DUAL SUPPLY XCVR 50 MBPS 5.5V XQFN8; 3D_Mechanical_Footprint_File: http://fcl.am.freescale.net/ALLEGRO/step/xqfn8_1p45x1p25mm.STEP; AGILE_PN: 312-80763; CAD_APPROVED: Yes; HEIGHT: 0.5MM; MFG_NAME01: NXP SEMICONDUCTORS; ROHS: Yes; VOLTAGE: 5.5V
U30 U32 U33 = 74LVCH1T45_6P: IC XCVR 1BIT 3-STATE DUAL 1.2-5.5V XSON6; AGILE_PN: 312-80758; CAD_APPROVED: Yes; HEIGHT: 0.5MM; MFG_NAME01: NEXPERIA; MFG_PN01: 74LVCH1T45GM,132; ROHS: Yes; VOLTAGE: 1.2-5.5V
U31 = 74LVC2T45DC_8P: IC XCVR DUAL SUPPLY 1.2-5.5V XSON8; 3D_Mechanical_Footprint_File: http://fcl.am.freescale.net/ALLEGRO/step/xson_8p.step; AGILE_PN: 312-83447; CAD_APPROVED: Yes; HEIGHT: 0.5MM; MFG_NAME01: Nexperia; Package Size: 1.95 x 1.00; ROHS: Yes; Supply Voltage: 1.2-5.5V; Temp Range: -40°C to +125°C; VOLTAGE: 1.2-5.5V
J23 = CONN_HDR_3X1: HDR 1X3 TH 100MIL SP 339H AU 100L; 3D_Mechanical_Footprint_File: http://fcl.am.freescale.net/ALLEGRO/step/hdr103.STEP; AGILE_PN: 210-75726; CAD_APPROVED: Yes; HEIGHT: 8.65MM; JUMPER (DEFAULT): NONE; MFG_NAME01: SAMTEC; MFG_PN01: TSW-103-07-G-S; Package Size: 7.62 x 2.54 mm; ROHS: Yes; SILK: IOREF; Temp Range: -55°C to +125°C; VOLTAGE: 450 - 550 VAC
J35 J37 J38 = CONN_HDR_8X2: HDR 2X8 SMT 100MIL CTR 380H AU; 3D_Mechanical_Footprint_File: http://fcl.am.freescale.net/ALLEGRO/step/hdr208_tsm_sm_450m.STEP; AGILE_PN: 211-79939; CAD_APPROVED: Yes; HEIGHT: 9.652MM; MFG_NAME01: SAMTEC; ROHS: Yes; Temp Range: -55°C to +125°C
J36 = CONN_HDR_10X2: HDR 2X10 SMT 100MIL CTR 385H AU; 3D_Mechanical_Footprint_File: http://fcl.am.freescale.net/ALLEGRO/step/con_tsm_20m_2p54_sm.STEP; AGILE_PN: 211-79940; CAD_APPROVED: Yes; HEIGHT: 9.78MM; MFG_NAME01: SAMTEC; MFG_PN01: TSM-110-01-F-DV; ROHS: Yes; Temp Range: -55°C to +125°C
J39 J40 = CONN_HDR_8X1: HDR 1X8 SMT 100MIL SP 398H AU; 3D_Mechanical_Footprint_File: http://fcl.am.freescale.net/ALLEGRO/step/hdr108_stag_tsm_smt.STEP; AGILE_PN: 211-78856; CAD_APPROVED: Yes; HEIGHT: 10.11MM; MFG_NAME01: SAMTEC; MFG_PN01: TSM-108-01-S-SV; Package Type: SMT; ROHS: Yes
J41 = CON_2X18_SKT: HDR 2X18 TH 100MIL CTR 343H AU 118L; 3D_Mechanical_Footprint_File: http://fcl.am.freescale.net/ALLEGRO/step/hdr218_2p54_a.STEP; AGILE_PN: 210-82170; ASSY_OPT: DNP; CAD_APPROVED: Yes; HEIGHT: 8.69MM; MFG_NAME01: WURTH ELEKTRONIK EISOS GMBH & CO. KG (ELECTRONIC & ELECTROMEHANICAL COMP); MFG_PN01: 61303621121; ROHS: Yes; Temp Range: -40°C to +105°C
J46 = CONN_HDR_10X1: CON 1X10 SKT SMT 100 MIL SP 297H AU; 3D_Mechanical_Footprint_File: http://fcl.am.freescale.net/ALLEGRO/step/con1x10_2p54_ssm.STEP; AGILE_PN: 211-79928; CAD_APPROVED: Yes; HEIGHT: 7.55MM; MFG_NAME01: SAMTEC; ROHS: Yes
J47-J51 = CONN_HDR_8X1: CON 1X8 SKT SMT 2.54MM SP 297H AU; 3D_Mechanical_Footprint_File: http://fcl.am.freescale.net/ALLEGRO/step/con1x8_skt_2p54_ssm.STEP; AGILE_PN: 211-79931; CAD_APPROVED: Yes; HEIGHT: 7.55MM; MFG_NAME01: SAMTEC; ROHS: Yes; Temp Range: -55°C to +125°C
J52 = CONN_HDR_3X1: HDR 1X3 TH 100MIL SP 339H AU 100L; 3D_Mechanical_Footprint_File: http://fcl.am.freescale.net/ALLEGRO/step/hdr103.STEP; AGILE_PN: 210-75726; CAD_APPROVED: Yes; HEIGHT: 8.65MM; JUMPER (DEFAULT): NONE; MFG_NAME01: SAMTEC; MFG_PN01: TSW-103-07-G-S; Package Size: 7.62 x 2.54 mm; ROHS: Yes; SILK: AREF; Temp Range: -55°C to +125°C; VOLTAGE: 450 - 550 VAC
J53 = HDR_1X2_TH: HDR 1X2 TH 100MIL SP 339H AU 98L; 3D_Mechanical_Footprint_File: http://fcl.am.freescale.net/ALLEGRO/step/hdr102_338h.STEP; AGILE_PN: 210-75439; CAD_APPROVED: YES; FPLIST: HDR102,SH_HDR102_BOTTOM; HEIGHT: 8.71 MM; JUMPER (DEFAULT): NONE; MFG_NAME01: SAMTEC; MFG_PN01: TSW-102-07-G-S; ROHS: Yes; SILK: PRD; Temp Range: -55°C to +125°C
R7 R91 R92 = RES: RES MF ZERO OHM 1/8W -- 0805; AGILE_PN: 470-75442; CAD_APPROVED: Yes; FPLIST: RC0805_OV,RC0805,RC0805_OV_3P,0805_CC; HEIGHT: 0.7 MM; MFG_NAME01: YAGEO AMERICA; MFG_PN01: RC0805JR-070RL; ROHS: Yes; Temp Range: –55 °C to +155 °C; Tolerance: 5%
R136 R137 R213 = RES_3PIN: RES MF ZERO OHM 1/10W -- 0603; AGILE_PN: 470-80866; CAD_APPROVED: Yes; FPLIST: RC0603_OV,RC0603,R603-X2,r603-x2_b,0603_CC,IND_0603HP_NSP,CC0603_OV_NSP; HEIGHT: 0.6MM; MFG_NAME01: YAGEO AMERICA; MFG_PN01: RC0603FR-070RL; ROHS: Yes; Temp Range: –55 °C to +155 °C
R139 R217 = RES: RES MF ZERO OHM 1/8W -- 0805; AGILE_PN: 470-75442; ASSY_OPT: DNP; CAD_APPROVED: Yes; FPLIST: RC0805_OV,RC0805,RC0805_OV_3P,0805_CC; HEIGHT: 0.7 MM; MFG_NAME01: YAGEO AMERICA; MFG_PN01: RC0805JR-070RL; ROHS: Yes; Temp Range: –55 °C to +155 °C; Tolerance: 5%
R148-R150 R152 R153 R155-R158 R229 R230 R249 = RES: RES MF ZERO OHM 1/10W -- 0603; AGILE_PN: 470-80866; CAD_APPROVED: Yes; FPLIST: RC0603_OV,RC0603,R603-X2,0603_CC,IND_0603HP_NSP,CC0603_OV_NSP; HEIGHT: 0.6MM; MFG_NAME01: YAGEO AMERICA; MFG_PN01: RC0603FR-070RL; ROHS: Yes; TOL: 5%; Temp Range: –55 °C to +155 °C

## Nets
GND: C48.2 C49.2 C50.2 C51.2 C66.2 C67.2 C68.2 C69.2 C70.2 C71.2 C72.2 C73.2 C74.2 C75.2 C76.2 C77.2 C78.2 C79.2 C98.2 C99.2 C100.2 C101.2 J21.3(A2) J21.5(A3) J35.11(A6) J35.13(A7) J36.8 J46.4 J47.6 J47.7 J63.2 J64.2 J65.2 J66.2 J67.2 P1.23 R52.2 R70.2 R89.2 R117.2 R122.2 R124.2 R138.2 R141.2 SJ1.1 SW1.1 SW1.2 SW4.1 SW4.2 U15.6(GND) U15.17(EP) U16.6(GND) U16.17(EP) U17.6(GND) U18.6(GND) U18.17(EP) U19.6(GND) U29.4(GND) U30.2(GND) U31.4(GND) U31.5(DIR) U32.2(GND) U33.2(GND) U34.5(GND) U35.4(GND) ; also on sheet 3 4 5 9 10
P3V3_BRD: C48.1 C50.1 C51.1 C77.1 C78.1 C99.1 C101.1 D3.A(ANODE) D4.A(ANODE) D5.A(ANODE) D6.A(ANODE) D7.A(ANODE) J21.1(A1) J23.1 J44.2 J52.1 R48.2 R49.2 R50.2 R51.1 R54.1 R56.1 R58.1 R59.1 R62.1 R68.1 R69.1 R71.1 R72.1 R91.1 R140.1 R142.1 U15.14(VCC) U16.14(VCC) U17.1(VCCA) U18.14(VCC) U19.1(VCCA) U34.10(VCC) U35.1(VCCA) ; also on sheet 3 9 10
P3V3_SDA: C66.1 C69.1 C71.1 C73.1 C75.1 J33.1 R111.1 R113.2 R118.1 R121.1 R125.1 U29.1(VCCA) U30.1(VCCA) U31.1(VCCA) U32.1(VCCA) U33.1(VCCA) ; also on sheet 5
P5V_BRD: J23.3 J52.3 R92.1 R139.1 ; also on sheet 3
P7V_JACK: J53.1 ; also on sheet 3
AD_ADDR_BIT0: J37.2(B1) ; also on sheet 9
AD_ADDR_BIT1: J37.4(B2) ; also on sheet 9
AD_CLK_AUX: R213.3 ; also on sheet 9
AD_I2CA_SCL: R162.2 R216.2 ; also on sheet 9
AD_I2CA_SDA: R161.2 R215.2 ; also on sheet 9
AD_I2CM_SCL: R153.2 R159.1 ; also on sheet 9
AD_I2CM_SDA: R152.2 R160.1 ; also on sheet 9
AD_I3CA_SCL: R167.2 ; also on sheet 9
AD_I3CA_SDA: R166.2 ; also on sheet 9
AD_INT_AUX: R137.3 ; also on sheet 9
AD_IO_AUX: R136.3 ; also on sheet 9
AD_NFC_AD1: R94.2 R221.1 R241.1 ; also on sheet 10
AD_NFC_AUX1: R154.1 R220.2 ; also on sheet 10
AD_NFC_AUX2: R151.1 R219.2 ; also on sheet 10
AD_NFC_AUX3: R214.2 ; also on sheet 10
AD_NFC_CLK: R222.1 ; also on sheet 10
AD_NFC_DWL_REQ: R149.1 ; also on sheet 10
AD_NFC_GPIO0: R186.1 R223.1 U17.9(B2)
AD_NFC_GPIO1: R187.1 R224.1 U17.10(B1)
AD_NFC_GPIO2: R182.1 R225.1 U17.8(B3)
AD_NFC_GPIO3: R183.1 R226.1 U17.7(B4)
AD_NFC_GPIO4: R184.1 R227.1 U19.10(B1)
AD_NFC_GPIO5: R185.1 R228.1 U19.9(B2)
AD_NFC_HOSTSEL0: R150.1 ; also on sheet 10
AD_NFC_HOSTSEL1: R229.1 ; also on sheet 10
AD_NFC_HOSTSEL2: R249.1 ; also on sheet 10
AD_NFC_IRQ: R148.1 ; also on sheet 10
AD_NFC_RESET: U35.2(A1) U35.3(A2) ; also on sheet 10
AD_NFC_VEN_RST: R230.1 ; also on sheet 10
AD_SPIA_CLK: R177.2 ; also on sheet 9
AD_SPIA_CS0: R178.2 ; also on sheet 9
AD_SPIA_MISO: R175.2 ; also on sheet 9
AD_SPIA_MOSI: R176.2 ; also on sheet 9
AD_SPIM_MISO: R129.1 R158.2 ; also on sheet 9
AD_SPIM_MOSI: R130.1 R157.2 ; also on sheet 9
AD_SPIM_SCLK: R128.1 R155.2 ; also on sheet 9
AD_SPIM_SSN: R131.1 R156.2 ; also on sheet 9
AD_SWO_CLK: R189.2 U19.8(B3)
AD_SWO_DIO: R188.2 U19.7(B4)
AD_UART_CTS: R145.1 ; also on sheet 9
AD_UART_RTS: R144.1 ; also on sheet 9
AD_UART_RX: R75.1 R231.1 ; also on sheet 9
AD_UART_TX: R74.1 R232.1 ; also on sheet 9
AD_VTUNE1: R39.1 ; also on sheet 4
AD_VTUNE2: R40.1 ; also on sheet 4
BYPASS_CLK_AUX: R213.1 ; also on sheet 9
BYPASS_INT_AUX: R137.1 ; also on sheet 9
BYPASS_IO_AUX: R136.1 ; also on sheet 9
HOST_5V: J35.9(A5) R139.2
HOST_AREF: J36.6 R218.1
HOST_GPIO_ADC0: J37.1(A1) R148.2 R198.2
HOST_GPIO_ADC1: J37.3(A2) R149.2 R199.2
HOST_GPIO_ADC2: J37.5(A3) R95.1 R150.2
HOST_GPIO_ADC3: J37.7(A4) R151.2 R200.2
HOST_GPIO_ADC4: J37.9(A5) R201.2
HOST_GPIO_ADC5: J37.11(A6) R202.2
HOST_GPIO_ADC6: J37.13(A7) R154.2 R203.2
HOST_GPIO_ADC7: J37.15(A8) R204.2
HOST_GPIO_ADC8: J39.1 R205.2
HOST_GPIO_ADC9: J39.2 R206.2
HOST_GPIO_ADC10: J39.3 R207.2
HOST_GPIO_ADC11: J39.4 R208.2
HOST_GPIO_CANRX: J39.7 R211.2
HOST_GPIO_CANTX: J39.8 R212.2
HOST_GPIO_DAC0: J39.5 R209.2 R241.2
HOST_GPIO_DAC1: J39.6 R210.2
HOST_GPIO_RX1: J40.6 R234.1
HOST_GPIO_RX2: J40.4 R147.1
HOST_GPIO_RX3: J40.2 R135.2
HOST_GPIO_TX1: J40.5 R233.1
HOST_GPIO_TX2: J40.3 R146.1
HOST_GPIO_TX3: J40.1 R134.2
HOST_IOREF: J35.3(A2) R217.2
HOST_RESET: J35.5(A3) J35.6(B3) R81.2
HOST_SCL: J40.8 R236.1
HOST_SDA: J40.7 R235.1
IOREF: C79.1 C98.1 C100.1 J23.2 R7.1 R143.1 R217.1 U17.11(VCCB) U19.11(VCCB) U35.8(VCCB) ; also on sheet 9 10
JTAG_TCK/SWDCLK: J21.4(B2) R52.1 U15.1(1Y0) U18.9(3Y0)
JTAG_TDI: J21.8(B4) R50.1 U15.9(3Y0)
JTAG_TDO: J17.1 J21.6(B3) R49.1
JTAG_TMS/SWDIO: J17.3 J21.2(B1) R48.1 U18.13(4Y0)
LPC_SPI_CS: J35.12(B6) R156.1
LPC_SPI_MISO: J35.16(B8) R158.1
LPC_SPI_MOSI: J35.14(B7) R157.1
LPC_SPI_SCK: J35.10(B5) R155.1
LVLRST_EN: R113.1 U29.5(OE)
NFC_JTAG_RST: D2.1(A1) D2.2(A2) R53.2 TP6.1(Pin1)
NFC_SWO_CLK: J32.2 U34.2(1Y1)
NFC_SWO_DIO: J31.2 U34.4(2Y1)
nRESET: D2.3(C) J21.10(B5)
PU-R_RST_B: C49.1 R51.2 R53.1
RST_TGTMCU_B: D9.C(CATHODE) J30.3 R112.2 R115.2 U29.7(B1) ; also on sheet 10
SDA_RST_LED: D9.A(ANODE) R114.2
SDA_RST_TGTMCU_J_B: J30.1 R111.2 R115.1 U29.2(A1) ; also on sheet 5
SDA_RX_EN: R117.1 R118.2 U30.5(DIR)
SDA_SPI0_SCK: TP25.1(Pin1) U33.3(A) ; also on sheet 5
SDA_SPI0_SIN: TP23.1(Pin1) U31.3(2A) ; also on sheet 5
SDA_SPI0_SOUT: TP24.1(Pin1) U32.3(A) ; also on sheet 5
SDA_SWD_EN: R123.1 ; also on sheet 5
SDA_SWD_EN_R: R123.2 R124.1 R125.2 U33.5(DIR)
SDA_SWD_OE: R120.1 ; also on sheet 5
SDA_SWD_OE_R: R120.2 R121.2 R122.1 U32.5(DIR)
SDA_VOUT33: J33.2 ; also on sheet 5
SENSOR_AREF: J46.3 J52.2 R218.2
SENSOR_GPIO_A0: J50.5 R39.2 R209.1
SENSOR_GPIO_A1: J50.6 R40.2 R210.1
SENSOR_GPIO_AN0: J48.1 R198.1
SENSOR_GPIO_AN1: J48.2 R199.1
SENSOR_GPIO_AN2: J48.3 R94.1 R95.2
SENSOR_GPIO_AN3: J48.4 R200.1
SENSOR_GPIO_AN4: J48.5 R201.1
SENSOR_GPIO_AN5: J48.6 R202.1
SENSOR_GPIO_AN6: J48.7 R203.1
SENSOR_GPIO_AN7: J48.8 R204.1
SENSOR_GPIO_AN8: J50.1 R205.1
SENSOR_GPIO_AN9: J50.2 R206.1
SENSOR_GPIO_AN10: J50.3 R207.1
SENSOR_GPIO_AN11: J50.4 R208.1
SENSOR_GPIO_CANRX: J50.8 R212.1
SENSOR_GPIO_CANTX: J50.7 R211.1
SENSOR_GPIO_RX1: J51.5 R213.2 R233.2
SENSOR_GPIO_RX2: J51.3 R136.2 R146.2
SENSOR_GPIO_RX3: J51.1 R134.1
SENSOR_GPIO_TX1: J51.6 R214.1 R234.2
SENSOR_GPIO_TX2: J51.4 R137.2 R147.2
SENSOR_GPIO_TX3: J51.2 R135.1
SENSOR_IOREF: J47.2 R7.2
SENSOR_RESET: J47.3 R143.2 U35.7(B1)
SENSOR_SCL: J51.8 R216.1 R236.2
SENSOR_SDA: J51.7 R215.1 R235.2
SENSOR_VIN: J47.8 J53.2
SW1_RST_B: C68.1 J30.2 SW4.3 SW4.4
SWD_CLK_TGTMCU_BUF: J32.1 U33.4(B)
SWD_DIO_TGTMCU_BUF: J31.1 U31.6(2B) U32.4(B)
TP_2102_A: TP19.1(Pin1) U29.3(A2)
TP_2102_B: TP20.1(Pin1) U29.6(B2)
UART1_RX_TGTMCU: R116.2 ; also on sheet 9
UART1_RX_TGTMCU_BUF: R116.1 U30.4(B)
UART1_RX_TGTMCU_R: TP21.1(Pin1) U30.3(A) ; also on sheet 5
UART1_TX_TGTMCU: R119.2 ; also on sheet 9
UART1_TX_TGTMCU_BUF: R119.1 U31.7(1B)
UART1_TX_TGTMCU_R: TP22.1(Pin1) U31.2(1A) ; also on sheet 5
V_TGTMCU: C67.1 C70.1 C72.1 C74.1 C76.1 J44.1 R112.1 R114.1 U29.8(VCCB) U30.6(VCCB) U31.8(VCCB) U32.6(VCCB) U33.6(VCCB)
N27500026: J38.2(B1) R225.2
N27500028: J38.4(B2) R226.2
N27500030: J38.6(B3) R227.2
N27500032: J38.8(B4) R228.2 R249.2
N27500034: J38.10(B5) R229.2
N27500036: J38.12(B6) R230.2
N27500038: J38.14(B7) R231.2
N27500040: J38.16(B8) R232.2
N27500086: J36.10 R177.1
N27500088: J36.12 R175.1
N27500090: J36.14 R176.1
N27500092: J36.16 R178.1
N27500094: J36.18 R223.2
N27500096: J36.20 R224.2
N27500120: J36.2 R162.1
N27500122: J36.4 R161.1
N27586305: J17.2 U15.5(2Y0)
N27586309: J17.4 U15.13(4Y0)
N27586433: P1.31 U15.16(1Z)
N27586452: U15.15(1Y1) U16.16(1Z)
N27586458: J21.9(A5) SJ1.2
N27586502: P1.28 U15.4(2Z)
N27586518: U15.3(2Y1) U16.4(2Z)
N27586545: J67.1 R56.2 U15.2(1S)
N27586571: P1.29 U15.8(3Z)
N27586587: U15.7(3Y1) U16.8(3Z)
N27586635: P1.30 U15.12(4Z)
N27586647: U15.11(4Y1) U16.12(4Z)
N27586665: J66.1 R54.2 U15.10(2S)
N27620041: J60.2(B1) U16.1(1Y0)
N27620044: J60.4(B2) U16.5(2Y0)
N27620047: J60.6(B3) U16.9(3Y0)
N27620050: J60.8(B4) U16.13(4Y0)
N27620262: D3.C(CATHODE) R61.1
N27620265: D4.C(CATHODE) R63.1
N27620268: D5.C(CATHODE) R65.1
N27620271: D6.C(CATHODE) R66.1
N27620274: R61.2 U16.15(1Y1)
N27620283: R63.2 U16.3(2Y1)
N27620292: R65.2 U16.7(3Y1)
N27620301: R66.2 U16.11(4Y1)
N27620375: J63.1 R59.2 U16.10(2S)
N27620473: J64.1 R62.2 U16.2(1S)
N27622538: J65.1 R72.2 U18.2(1S)
N27622554: R69.2 R70.1 U18.10(2S)
N27622661: P1.24 U18.8(3Z)
N27622664: P1.25 U18.12(4Z)
N27623072: P1.33 U18.4(2Z)
N27623075: P1.32 U18.16(1Z)
N27623200: J60.10(B5) U18.1(1Y0)
N27623206: J60.12(B6) U18.5(2Y0)
N27623271: D7.C(CATHODE) R67.1
N27623273: R67.2 U18.15(1Y1)
N27623357: R68.2 SW1.3 SW1.4 U18.3(2Y1)
N27623670: U18.7(3Y1) U34.9(1Z)
N27623673: U18.11(4Y1) U34.6(2Z)
N27644154: R71.2 R89.1 U19.12(OE)
N27644972: R58.2 R138.1 U17.12(OE)
N27644976: J60.1(A1) U17.2(A1)
N27644980: J60.3(A2) U17.3(A2)
N27644984: J60.5(A3) U17.4(A3)
N27644988: J60.7(A4) U17.5(A4)
N27727965: J46.1 R159.2
N27727993: J46.2 R160.2
N27728012: J46.5 R128.2
N27728017: J46.6 R129.2
N27728024: J46.7 R130.2
N27728034: J46.8 R131.2
N27728045: J46.9 R186.2
N27728062: J46.10 R187.2
N27728109: J49.1 R182.2
N27728120: J49.2 R183.2
N27728131: J49.3 R184.2
N27728142: J49.4 R185.2
N27728153: J49.5 R219.1
N27728164: J49.6 R220.1
N27728175: J49.7 R74.2
N27728186: J49.8 R75.2
N27739329: R140.2 R141.1 U34.7(2S) U34.8(1S)
N27739877: U19.4(A3) U34.1(1Y0)
N27739886: U19.5(A4) U34.3(2Y0)
N27740241: R142.2 U35.5(OE)
N27895236: R81.1 U35.6(B2)
N27895817: J47.4 R91.2
N27895820: J47.5 R92.2
N27946345: J37.10(B5) R152.1 R166.1
N27946347: J37.12(B6) R153.1 R167.1
N27947233: J38.13(A7) R144.2
N27947327: J36.3 R145.2
N27971242: J37.8(B4) R222.2
N27978619: J36.15 R221.2
N28110322: J35.2(B1) R188.1
N28110325: J35.4(B2) R189.1
N28111335: J60.9(A5) U19.2(A1)
N28111344: J60.11(A6) U19.3(A2)

Not connected (* = marked no-connect by the designer): J21 7(A4)*; J35 1(A1)* 7(A4)* 8(B4)* 15(A8)*; J36 1* 5* 7* 9* 11* 13* 17* 19*; J37 6(B3)* 14(B7)* 16(B8)*; J38 1(A1)* 3(A2)* 5(A3)* 7(A4)* 9(A5)* 11(A6)* 15(A8)*; J41 1* 2* 3* 4* 5* 6* 7* 8* 9* 10* 11* 12* 13* 14* 15* 16* 17* 18* 19* 20* 21* 22* 23* 24* 25* 26* 27* 28* 29* 30* 31* 32* 33* 34* 35* 36*; J47 1*

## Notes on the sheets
sheet 6
- RESET
- I/O POWER
  INPUT
- i
- path
- This power rail is supported
  from 1.8V to 5V
- Power should be provided
  to this rail for the logic
  related to your platform I/O
- 1-2: Default.
  2-3: Reset signal direct to the MCU,
  to use when OpenSDA is not powered.
- RST Push Button
  Bypass
- SHORTING HEADER ON BOTTOM LAYER
- TARGET MCU
  INTERFACE
  SIGNALS
- Output to system
  from Level shifter
- Output to system
  from Level shifter
- Isolation
  Resistors
- Input to Level shifter
  from system
- * Default 1-2
- * Default 1-2
- OPEN SDA
  POWER OUTPUTS
- OPEN SDA
  INPUT POWER
- i
- i
- path
- path
- Note: You can power openSDA
  with your own power supplies
  by replacing this rail
  (SDA_VOUT33)
  with your 3.3V power supply rail
- 3.3VDC, 10mA should be provided
  to this rail (P3V3_SDA)
  in order to power openSDA
  module
- SHORTING HEADER ON BOTTOM LAYER
- SDA_VOUT33 can provide up to 120mA
  of power at 3.3VDC to your system
- Isolation and level shift stage
  (for 1.8 to 5V compatibility)
- PU/PD LOGIC (DIR PIN):
  BUFFER IS TRISTATED WHEN
  P3V3_SDA IS UNPOWERED
sheet 7
- i
- Note:
  Typically PN76xx board as leader when mates with TOP board;
  PN76xx board as follower when mates with BOTTOM board.
  Please check the connections (power, logic, direction, etc.) carefully
  before PN76xx board mates with TOP and BOTTOM boards at the same time.
- TOP BOARD INTERFACE (ARDUINO SENSOR, TDAEV8035, etc.)
- SENSOR I2C_SCL FOLLOWER
- CAKE8035_CMDVCCN
- SENSOR I2C_SDA FOLLOWER
- CAKE8035_VDDI
- CAKE8035_RSTIN
- CAKE8035_EN5V_3VN
- SENSOR SPI_SCLK FOLLOWER
- CAKE8034_VDDP
- CAKE8035_CLKDIV1
- CAKE8035_CLKDIV2
- SENSOR SPI_MISO FOLLOWER
- SENSOR SPI_MOSI FOLLOWER
- CAKE8035_GND
- CAKE8035_EN1V8N
- SENSOR SPI_SSN FOLLOWER
- CAKE8035_GND
- SENSOR GPIO
- SENSOR GPIO
- i
- Note: if sensor board, base board, host board are sandwich stacked
  Make sure host IOREF same as sensor IOREF before populate R81
- SENSOR GPIO
- SENSOR GPIO
- SENSOR GPIO
- SENSOR GPIO
- CAKE8035_AUX2UC
- SENSOR GPIO
- i
- CAKE8035_AUX1UC
- SENSOR GPIO
- Note:
  AUX1 and AUX2 as digital IO is only used for 3.3V logic.
  AUX1 and AUX2 could be analog test bus.
- SENSOR UART RX
- SENSOR UART TX
- CAKE8035_IOUC
- CAKE8035_OFFN
- CAKE8035_XTAL1
- i
- Note:
  AUX3 as digital IO is only used for 3.3V logic.
  AUX3 could be analog test bus.
- i
- Note: 0ohm placement
  All 0ohm resistors should be placed in order to short signal stubs when signal has multiple connects to pins.
- BOTTOM BOARD INTERFACE (ARDUINO UNO/DUE, LPC55S16-EVK)
- i
- Note:
  Typically PN76xx board as leader when mates with TOP board;
  PN76xx board as follower when mates with BOTTOM board.
  Please check the connections (power, logic, direction, etc.) carefully
  before PN76xx board mates with TOP and BOTTOM boards at the same time.
- i
- Note: OUTSIDE pins ONLY for LPC55S16-EVK
  Currently only support SWD debug and SPI follower
- HOST I2C_SCL
- HOST I2C_SDA
- LPC UART RTS
- HOST SPI_SCLK
- HOST_3V_UNUSED
- HOST SPI_MISO
- HOST SPI_MOSI
- HOST SPI_CS
- LPC SCT0_OUT2
- HOST GPIO
- HOST_VIN_UNUSED
- HOST GPIO
- i
- Note: Populate R139 and do not populate any jumper in J3,
  if P5V_BRD from leader (aurnido board) needs to be used.
- HOST GPIO
- HOST GPIO
- HOST GPIO
- LPC SCT0_OUT6
- HOST GPIO
- HOST GPIO
- HOST GPIO
- HOST UART TX
- LPC UART CTS
- HOST UART RX
sheet 8
- JTAG/SWD NFCC
- Layout Note: Add on silk
  JTAG: (1-2) & (3-4)
  SWD: (2-3)
- Note:
  JTAG for external
  JLINK default
- LPC-Link2: Pinout
- info:
  cut/remove pin 7
- GPIO1
- [JTAG_TCK/SWDCLK]
- GPIO0
- [JTAG_TDO/SWDIO]
- [JTAG_TDI]
- GPIO2
- [JTAG_TMS]
- GPIO3
- i
- Note:(NX3DV3899HR)
  SEL: 0 (Y0), 1 (default Y1)
- PNEV7642MA INTERFACE
- i
- Note:(NX3DV3899HR)
  SEL: 0 (Y0), 1 (default Y1)
- i
- Note:(NX3DV3899HR)
  SEL: 0 (default Y0), 1 (Y1)
- i
- Note:(NX3DV3899HR)
  SEL: 0 (default Y0), 1 (Y1)
- GPIO4
- GPIO5
- SWDCLK
- i
- SWDIO
- Note:LED RED
  Controlled by PWM
- i
- Note:(NX3DV3899HR)
  SEL: 0 (default Y0), 1 (Y1)
- i
- Note:(NX3DV3899HR)
  SEL: 0 (Y0), 1 (default Y1)
- GND
- i
- Note:(NX3L2267)
  SEL: 0 (Y0), 1 (default Y1)
